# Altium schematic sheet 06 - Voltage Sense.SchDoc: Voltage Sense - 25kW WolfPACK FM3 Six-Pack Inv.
size 431 x 279 mm; Date: 07/2023; DocumentNumber: CRD25DA12N-FMC; Revision: 1.1; SheetNumber: 6; SheetTotal: 8; SheetSize: B
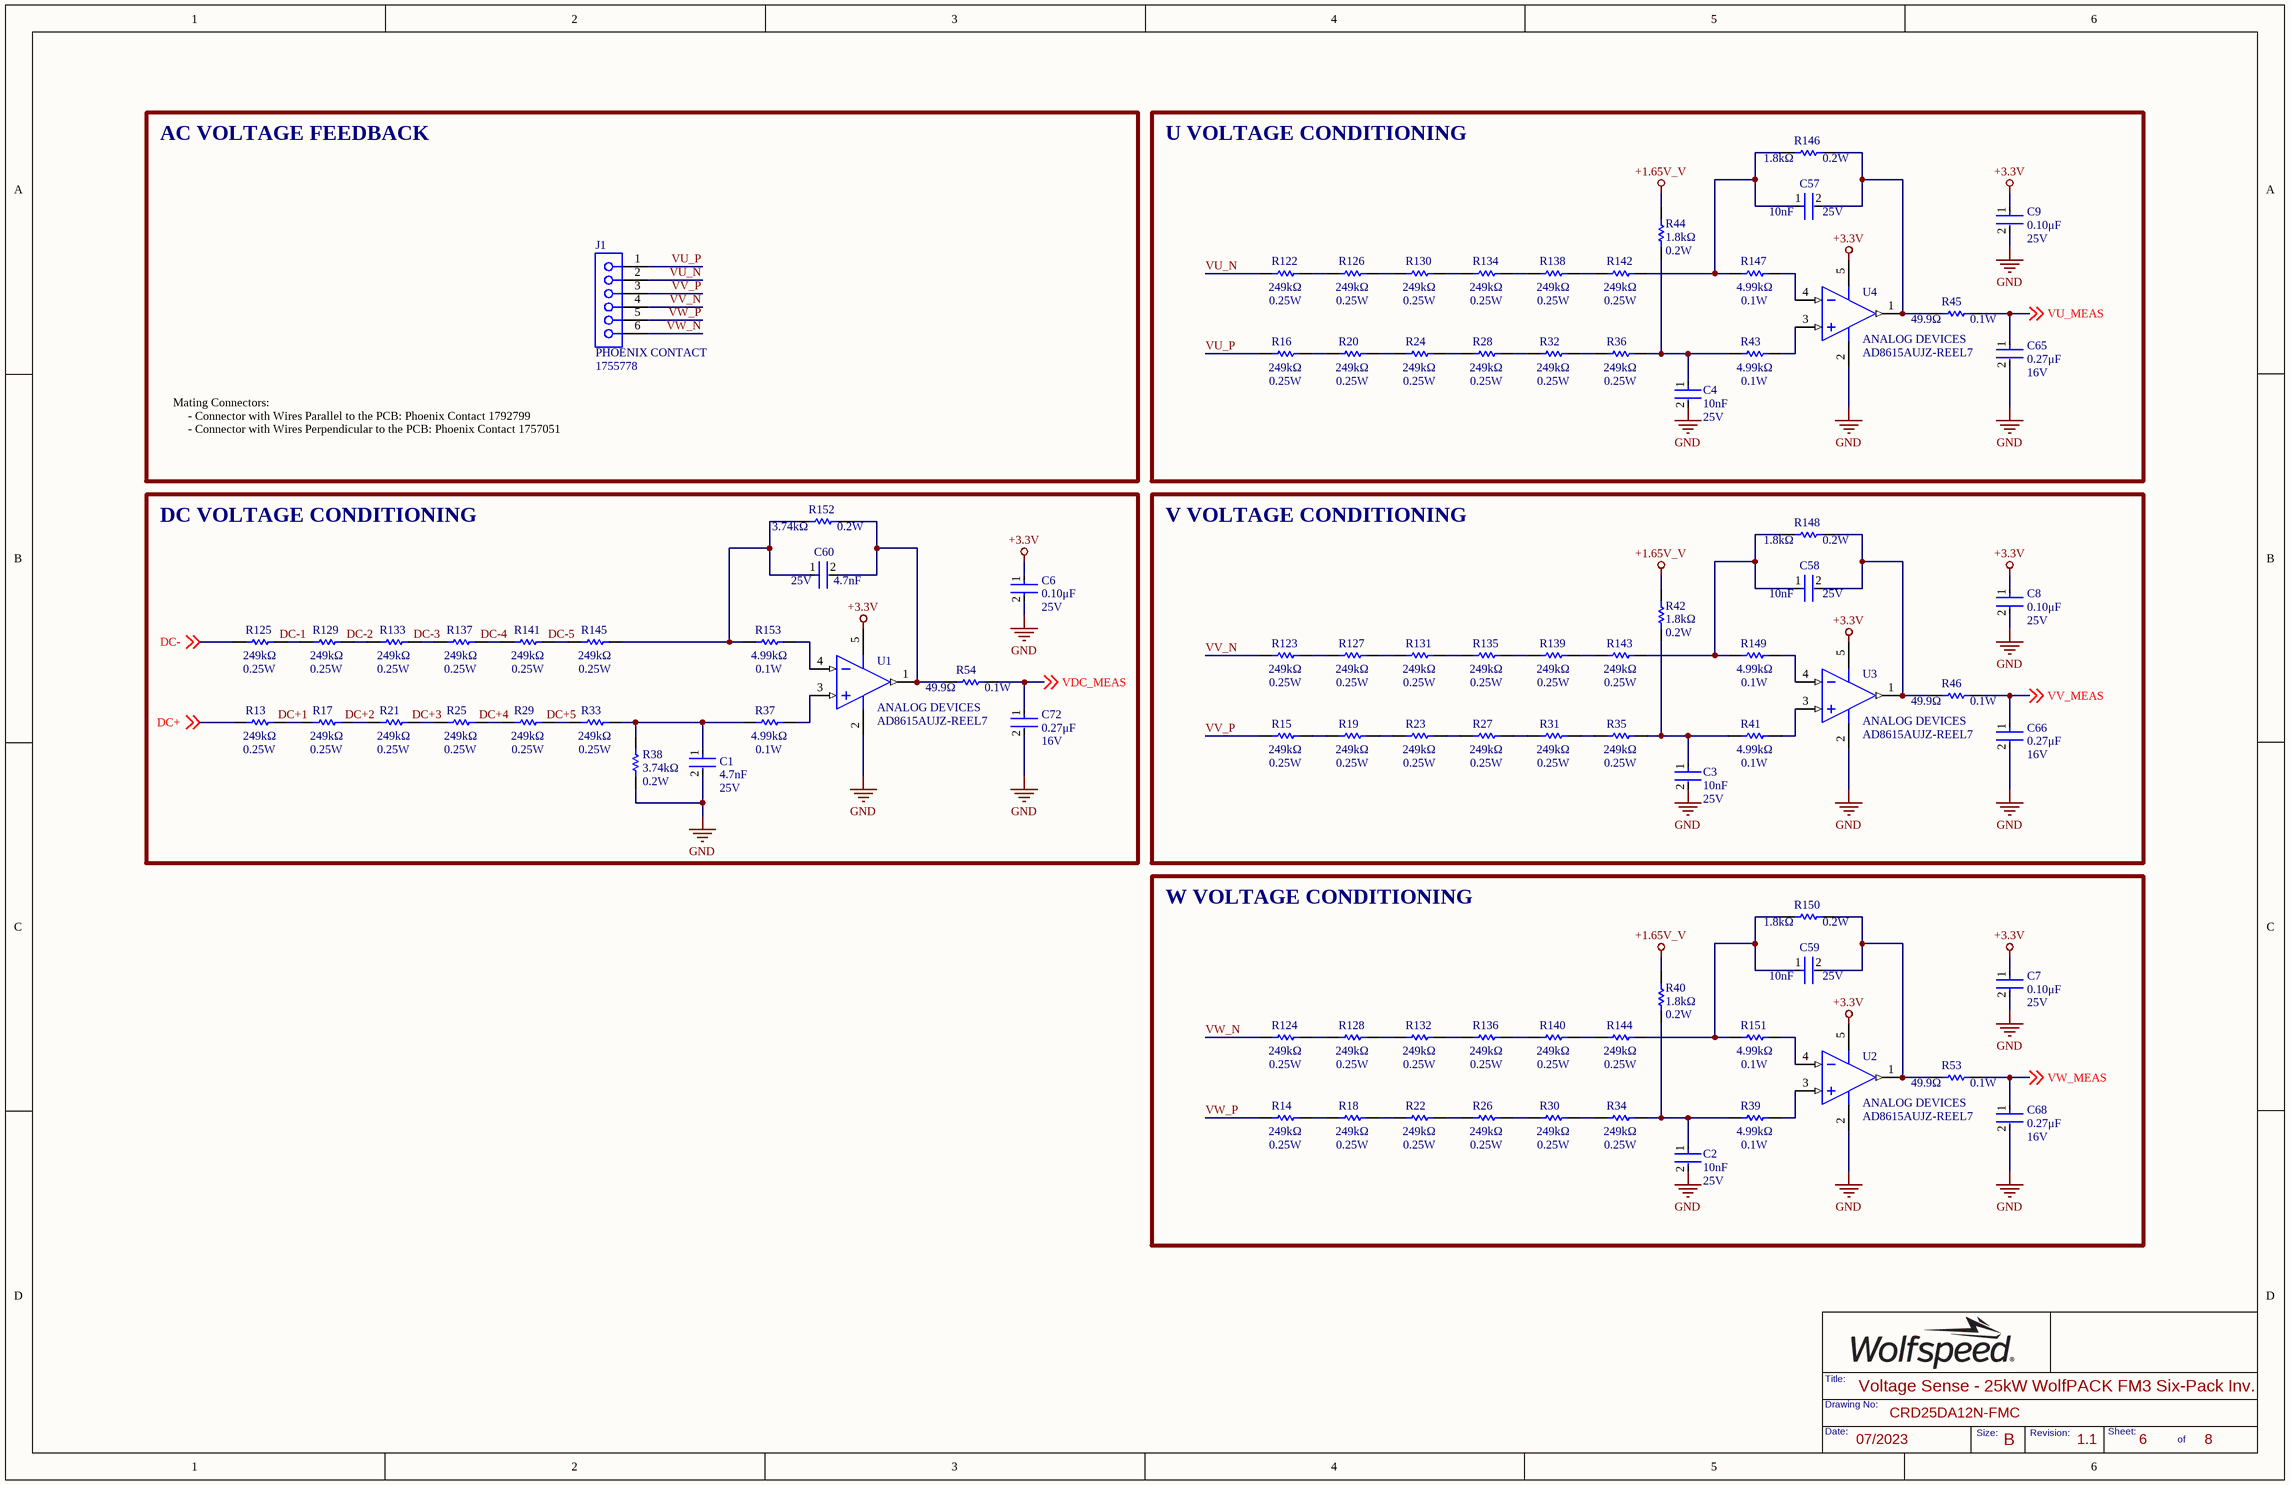
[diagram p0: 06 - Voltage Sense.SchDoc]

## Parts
C1  Voltage Rating: 25V  Capacitance: 4.7nF  [FP-C0603C-CF-IPC_B]  (hidden comment: C0603C472K3RAC7867)
C2  value 10nF  Voltage Rating: 25V  [FP-C0603C-CF-IPC_B]  (hidden comment: CL10B103KA8WPNC)
C3  value 10nF  Voltage Rating: 25V  [FP-C0603C-CF-IPC_B]  (hidden comment: CL10B103KA8WPNC)
C4  value 10nF  Voltage Rating: 25V  [FP-C0603C-CF-IPC_B]  (hidden comment: CL10B103KA8WPNC)
C6  Voltage Rating: 25V  Capacitance: 0.10μF  [FP-C0603C-CF-IPC_B]  (hidden comment: C0603C104K3RACTU)
C7  Voltage Rating: 25V  Capacitance: 0.10μF  [FP-C0603C-CF-IPC_B]  (hidden comment: C0603C104K3RACTU)
C8  Voltage Rating: 25V  Capacitance: 0.10μF  [FP-C0603C-CF-IPC_B]  (hidden comment: C0603C104K3RACTU)
C9  Voltage Rating: 25V  Capacitance: 0.10μF  [FP-C0603C-CF-IPC_B]  (hidden comment: C0603C104K3RACTU)
C57  value 10nF  Voltage Rating: 25V  [FP-C0603C-CF-IPC_B]  (hidden comment: CL10B103KA8WPNC)
C58  value 10nF  Voltage Rating: 25V  [FP-C0603C-CF-IPC_B]  (hidden comment: CL10B103KA8WPNC)
C59  value 10nF  Voltage Rating: 25V  [FP-C0603C-CF-IPC_B]  (hidden comment: CL10B103KA8WPNC)
C60  Voltage Rating: 25V  Capacitance: 4.7nF  [FP-C0603C-CF-IPC_B]  (hidden comment: C0603C472K3RAC7867)
C65  Voltage Rating (DC): 16V  Capacitance: 0.27μF  [FP-GCM188-0_1-IPC_A]  (hidden comment: GCM188R71C274KA37D)
C66  Voltage Rating (DC): 16V  Capacitance: 0.27μF  [FP-GCM188-0_1-IPC_A]  (hidden comment: GCM188R71C274KA37D)
C68  Voltage Rating (DC): 16V  Capacitance: 0.27μF  [FP-GCM188-0_1-IPC_A]  (hidden comment: GCM188R71C274KA37D)
C72  Voltage Rating (DC): 16V  Capacitance: 0.27μF  [FP-GCM188-0_1-IPC_A]  (hidden comment: GCM188R71C274KA37D)
J1  1755778  Manufacturer Print: PHOENIX CONTACT  [1755778]
R13  Resistance: 249kΩ  Power: 0.25W  [RESC3216X65X50NL15T25]  (hidden comment: TNPW1206249KBEEA)
R14  Resistance: 249kΩ  Power: 0.25W  [RESC3216X65X50NL15T25]  (hidden comment: TNPW1206249KBEEA)
R15  Resistance: 249kΩ  Power: 0.25W  [RESC3216X65X50NL15T25]  (hidden comment: TNPW1206249KBEEA)
R16  Resistance: 249kΩ  Power: 0.25W  [RESC3216X65X50NL15T25]  (hidden comment: TNPW1206249KBEEA)
R17  Resistance: 249kΩ  Power: 0.25W  [RESC3216X65X50NL15T25]  (hidden comment: TNPW1206249KBEEA)
R18  Resistance: 249kΩ  Power: 0.25W  [RESC3216X65X50NL15T25]  (hidden comment: TNPW1206249KBEEA)
R19  Resistance: 249kΩ  Power: 0.25W  [RESC3216X65X50NL15T25]  (hidden comment: TNPW1206249KBEEA)
R20  Resistance: 249kΩ  Power: 0.25W  [RESC3216X65X50NL15T25]  (hidden comment: TNPW1206249KBEEA)
R21  Resistance: 249kΩ  Power: 0.25W  [RESC3216X65X50NL15T25]  (hidden comment: TNPW1206249KBEEA)
R22  Resistance: 249kΩ  Power: 0.25W  [RESC3216X65X50NL15T25]  (hidden comment: TNPW1206249KBEEA)
R23  Resistance: 249kΩ  Power: 0.25W  [RESC3216X65X50NL15T25]  (hidden comment: TNPW1206249KBEEA)
R24  Resistance: 249kΩ  Power: 0.25W  [RESC3216X65X50NL15T25]  (hidden comment: TNPW1206249KBEEA)
R25  Resistance: 249kΩ  Power: 0.25W  [RESC3216X65X50NL15T25]  (hidden comment: TNPW1206249KBEEA)
R26  Resistance: 249kΩ  Power: 0.25W  [RESC3216X65X50NL15T25]  (hidden comment: TNPW1206249KBEEA)
R27  Resistance: 249kΩ  Power: 0.25W  [RESC3216X65X50NL15T25]  (hidden comment: TNPW1206249KBEEA)
R28  Resistance: 249kΩ  Power: 0.25W  [RESC3216X65X50NL15T25]  (hidden comment: TNPW1206249KBEEA)
R29  Resistance: 249kΩ  Power: 0.25W  [RESC3216X65X50NL15T25]  (hidden comment: TNPW1206249KBEEA)
R30  Resistance: 249kΩ  Power: 0.25W  [RESC3216X65X50NL15T25]  (hidden comment: TNPW1206249KBEEA)
R31  Resistance: 249kΩ  Power: 0.25W  [RESC3216X65X50NL15T25]  (hidden comment: TNPW1206249KBEEA)
R32  Resistance: 249kΩ  Power: 0.25W  [RESC3216X65X50NL15T25]  (hidden comment: TNPW1206249KBEEA)
R33  Resistance: 249kΩ  Power: 0.25W  [RESC3216X65X50NL15T25]  (hidden comment: TNPW1206249KBEEA)
R34  Resistance: 249kΩ  Power: 0.25W  [RESC3216X65X50NL15T25]  (hidden comment: TNPW1206249KBEEA)
R35  Resistance: 249kΩ  Power: 0.25W  [RESC3216X65X50NL15T25]  (hidden comment: TNPW1206249KBEEA)
R36  Resistance: 249kΩ  Power: 0.25W  [RESC3216X65X50NL15T25]  (hidden comment: TNPW1206249KBEEA)
R37  Power Rating: 0.1W  Resistance: 4.99kΩ  [FP-MCR03-IPC_B]  (hidden comment: RC0603FR-074K99L)
R38  Max Power Dissipation: 0.2W  Resistance: 3.74kΩ  [FP-MCR03-IPC_B]  (hidden comment: ERJ-PB3B3741V)
R39  Power Rating: 0.1W  Resistance: 4.99kΩ  [FP-MCR03-IPC_B]  (hidden comment: RC0603FR-074K99L)
R40  Resistance: 1.8kΩ  Max Power Dissipation: 0.2W  [FP-MCR03-IPC_B]  (hidden comment: ERJ-PB3B1801V)
R41  Power Rating: 0.1W  Resistance: 4.99kΩ  [FP-MCR03-IPC_B]  (hidden comment: RC0603FR-074K99L)
R42  Resistance: 1.8kΩ  Max Power Dissipation: 0.2W  [FP-MCR03-IPC_B]  (hidden comment: ERJ-PB3B1801V)
R43  Power Rating: 0.1W  Resistance: 4.99kΩ  [FP-MCR03-IPC_B]  (hidden comment: RC0603FR-074K99L)
R44  Resistance: 1.8kΩ  Max Power Dissipation: 0.2W  [FP-MCR03-IPC_B]  (hidden comment: ERJ-PB3B1801V)
R45  Resistance: 49.9Ω  Power Rating: 0.1W  [FP-MCR03-IPC_B]  (hidden comment: ERJ-3EKF49R9V)
R46  Resistance: 49.9Ω  Power Rating: 0.1W  [FP-MCR03-IPC_B]  (hidden comment: ERJ-3EKF49R9V)
R53  Resistance: 49.9Ω  Power Rating: 0.1W  [FP-MCR03-IPC_B]  (hidden comment: ERJ-3EKF49R9V)
R54  Resistance: 49.9Ω  Power Rating: 0.1W  [FP-MCR03-IPC_B]  (hidden comment: ERJ-3EKF49R9V)
R122  Resistance: 249kΩ  Power: 0.25W  [RESC3216X65X50NL15T25]  (hidden comment: TNPW1206249KBEEA)
R123  Resistance: 249kΩ  Power: 0.25W  [RESC3216X65X50NL15T25]  (hidden comment: TNPW1206249KBEEA)
R124  Resistance: 249kΩ  Power: 0.25W  [RESC3216X65X50NL15T25]  (hidden comment: TNPW1206249KBEEA)
R125  Resistance: 249kΩ  Power: 0.25W  [RESC3216X65X50NL15T25]  (hidden comment: TNPW1206249KBEEA)
R126  Resistance: 249kΩ  Power: 0.25W  [RESC3216X65X50NL15T25]  (hidden comment: TNPW1206249KBEEA)
R127  Resistance: 249kΩ  Power: 0.25W  [RESC3216X65X50NL15T25]  (hidden comment: TNPW1206249KBEEA)
R128  Resistance: 249kΩ  Power: 0.25W  [RESC3216X65X50NL15T25]  (hidden comment: TNPW1206249KBEEA)
R129  Resistance: 249kΩ  Power: 0.25W  [RESC3216X65X50NL15T25]  (hidden comment: TNPW1206249KBEEA)
R130  Resistance: 249kΩ  Power: 0.25W  [RESC3216X65X50NL15T25]  (hidden comment: TNPW1206249KBEEA)
R131  Resistance: 249kΩ  Power: 0.25W  [RESC3216X65X50NL15T25]  (hidden comment: TNPW1206249KBEEA)
R132  Resistance: 249kΩ  Power: 0.25W  [RESC3216X65X50NL15T25]  (hidden comment: TNPW1206249KBEEA)
R133  Resistance: 249kΩ  Power: 0.25W  [RESC3216X65X50NL15T25]  (hidden comment: TNPW1206249KBEEA)
R134  Resistance: 249kΩ  Power: 0.25W  [RESC3216X65X50NL15T25]  (hidden comment: TNPW1206249KBEEA)
R135  Resistance: 249kΩ  Power: 0.25W  [RESC3216X65X50NL15T25]  (hidden comment: TNPW1206249KBEEA)
R136  Resistance: 249kΩ  Power: 0.25W  [RESC3216X65X50NL15T25]  (hidden comment: TNPW1206249KBEEA)
R137  Resistance: 249kΩ  Power: 0.25W  [RESC3216X65X50NL15T25]  (hidden comment: TNPW1206249KBEEA)
R138  Resistance: 249kΩ  Power: 0.25W  [RESC3216X65X50NL15T25]  (hidden comment: TNPW1206249KBEEA)
R139  Resistance: 249kΩ  Power: 0.25W  [RESC3216X65X50NL15T25]  (hidden comment: TNPW1206249KBEEA)
R140  Resistance: 249kΩ  Power: 0.25W  [RESC3216X65X50NL15T25]  (hidden comment: TNPW1206249KBEEA)
R141  Resistance: 249kΩ  Power: 0.25W  [RESC3216X65X50NL15T25]  (hidden comment: TNPW1206249KBEEA)
R142  Resistance: 249kΩ  Power: 0.25W  [RESC3216X65X50NL15T25]  (hidden comment: TNPW1206249KBEEA)
R143  Resistance: 249kΩ  Power: 0.25W  [RESC3216X65X50NL15T25]  (hidden comment: TNPW1206249KBEEA)
R144  Resistance: 249kΩ  Power: 0.25W  [RESC3216X65X50NL15T25]  (hidden comment: TNPW1206249KBEEA)
R145  Resistance: 249kΩ  Power: 0.25W  [RESC3216X65X50NL15T25]  (hidden comment: TNPW1206249KBEEA)
R146  Resistance: 1.8kΩ  Max Power Dissipation: 0.2W  [FP-MCR03-IPC_B]  (hidden comment: ERJ-PB3B1801V)
R147  Power Rating: 0.1W  Resistance: 4.99kΩ  [FP-MCR03-IPC_B]  (hidden comment: RC0603FR-074K99L)
R148  Resistance: 1.8kΩ  Max Power Dissipation: 0.2W  [FP-MCR03-IPC_B]  (hidden comment: ERJ-PB3B1801V)
R149  Power Rating: 0.1W  Resistance: 4.99kΩ  [FP-MCR03-IPC_B]  (hidden comment: RC0603FR-074K99L)
R150  Resistance: 1.8kΩ  Max Power Dissipation: 0.2W  [FP-MCR03-IPC_B]  (hidden comment: ERJ-PB3B1801V)
R151  Power Rating: 0.1W  Resistance: 4.99kΩ  [FP-MCR03-IPC_B]  (hidden comment: RC0603FR-074K99L)
R152  Max Power Dissipation: 0.2W  Resistance: 3.74kΩ  [FP-MCR03-IPC_B]  (hidden comment: ERJ-PB3B3741V)
R153  Power Rating: 0.1W  Resistance: 4.99kΩ  [FP-MCR03-IPC_B]  (hidden comment: RC0603FR-074K99L)
U1  Manufacturer: ANALOG DEVICES  [ADI-UJ-5_M]  (hidden comment: AD8615AUJZ-REEL7)
U2  Manufacturer: ANALOG DEVICES  [ADI-UJ-5_M]  (hidden comment: AD8615AUJZ-REEL7)
U3  Manufacturer: ANALOG DEVICES  [ADI-UJ-5_M]  (hidden comment: AD8615AUJZ-REEL7)
U4  Manufacturer: ANALOG DEVICES  [ADI-UJ-5_M]  (hidden comment: AD8615AUJZ-REEL7)

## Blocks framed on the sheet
AC VOLTAGE FEEDBACK: J1
U VOLTAGE CONDITIONING: C4 C9 C57 C65 R16 R20 R24 R28 R32 R36 R43-R45 R122 R126 R130 R134 R138 R142 R146 R147 U4
DC VOLTAGE CONDITIONING: C1 C6 C60 C72 R13 R17 R21 R25 R29 R33 R37 R38 R54 R125 R129 R133 R137 R141 R145 R152 R153 U1
V VOLTAGE CONDITIONING: C3 C8 C58 C66 R15 R19 R23 R27 R31 R35 R41 R42 R46 R123 R127 R131 R135 R139 R143 R148 R149 U3
W VOLTAGE CONDITIONING: C2 C7 C59 C68 R14 R18 R22 R26 R30 R34 R39 R40 R53 R124 R128 R132 R136 R140 R144 R150 R151 U2

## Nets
+1.65V_V: R40.2 R42.2 R44.2
+3.3V: C6.1 C7.1 C8.1 C9.1 U1.5(+V) U2.5(+V) U3.5(+V) U4.5(+V)
GND: C1.2 C2.2 C3.2 C4.2 C6.2 C7.2 C8.2 C9.2 C65.2 C66.2 C68.2 C72.2 R38.1 U1.2(-V) U2.2(-V) U3.2(-V) U4.2(-V)
DC+: R13.1 ; off-sheet DC+
DC+1: R13.2 R17.1
DC+2: R17.2 R21.1
DC+3: R21.2 R25.1
DC+4: R25.2 R29.1
DC+5: R29.2 R33.1
DC-: R125.1 ; off-sheet DC-
DC-1: R125.2 R129.1
DC-2: R129.2 R133.1
DC-3: R133.2 R137.1
DC-4: R137.2 R141.1
DC-5: R141.2 R145.1
VDC_MEAS: C72.1 R54.2 ; off-sheet VDC_MEAS
VU_MEAS: C65.1 R45.2 ; off-sheet VU_MEAS
VU_N: J1.2 R122.1
VU_P: J1.1 R16.1
VV_MEAS: C66.1 R46.2 ; off-sheet VV_MEAS
VV_N: J1.4 R123.1
VV_P: J1.3 R15.1
VW_MEAS: C68.1 R53.2 ; off-sheet VW_MEAS
VW_N: J1.6 R124.1
VW_P: J1.5 R14.1
NetC1_1: C1.1 R33.2 R37.1 R38.2
NetC2_1: C2.1 R34.2 R39.1 R40.1
NetC3_1: C3.1 R35.2 R41.1 R42.1
NetC4_1: C4.1 R36.2 R43.1 R44.1
NetC57_1: C57.1 R142.2 R146.2 R147.1
NetC57_2: C57.2 R45.1 R146.1 U4.1(OUT)
NetC58_1: C58.1 R143.2 R148.2 R149.1
NetC58_2: C58.2 R46.1 R148.1 U3.1(OUT)
NetC59_1: C59.1 R144.2 R150.2 R151.1
NetC59_2: C59.2 R53.1 R150.1 U2.1(OUT)
NetC60_1: C60.1 R145.2 R152.1 R153.1
NetC60_2: C60.2 R54.1 R152.2 U1.1(OUT)
NetR14_2: R14.2 R18.1
NetR15_2: R15.2 R19.1
NetR16_2: R16.2 R20.1
NetR18_2: R18.2 R22.1
NetR19_2: R19.2 R23.1
NetR20_2: R20.2 R24.1
NetR22_2: R22.2 R26.1
NetR23_2: R23.2 R27.1
NetR24_2: R24.2 R28.1
NetR26_2: R26.2 R30.1
NetR27_2: R27.2 R31.1
NetR28_2: R28.2 R32.1
NetR30_2: R30.2 R34.1
NetR31_2: R31.2 R35.1
NetR32_2: R32.2 R36.1
NetR37_2: R37.2 U1.3(+IN)
NetR39_2: R39.2 U2.3(+IN)
NetR41_2: R41.2 U3.3(+IN)
NetR43_2: R43.2 U4.3(+IN)
NetR122_2: R122.2 R126.1
NetR123_2: R123.2 R127.1
NetR124_2: R124.2 R128.1
NetR126_2: R126.2 R130.1
NetR127_2: R127.2 R131.1
NetR128_2: R128.2 R132.1
NetR130_2: R130.2 R134.1
NetR131_2: R131.2 R135.1
NetR132_2: R132.2 R136.1
NetR134_2: R134.2 R138.1
NetR135_2: R135.2 R139.1
NetR136_2: R136.2 R140.1
NetR138_2: R138.2 R142.1
NetR139_2: R139.2 R143.1
NetR140_2: R140.2 R144.1
NetR147_2: R147.2 U4.4(-IN)
NetR149_2: R149.2 U3.4(-IN)
NetR151_2: R151.2 U2.4(-IN)
NetR153_2: R153.2 U1.4(-IN)

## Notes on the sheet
- Mating Connectors:
  - Connector with Wires Parallel to the PCB: Phoenix Contact 1792799
  - Connector with Wires Perpendicular to the PCB: Phoenix Contact 1757051

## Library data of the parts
C1 C60 = C0603C472K3RAC7867: CAP CER 4700PF 25V 10% X7R 0603; Manufacturer: KEMET; Manufacturer Part Number: C0603C472K3RACTU; Dielectric Material: Ceramic; Value: 4.7nF
C2-C4 C57-C59 = CL10B103KA8WPNC: CAP CER 10000PF 25V X7R 0603; Manufacturer: SAMSUNG; Tolerance: 10%
C6-C9 = CMP-2006-03057-2: CAP CER 0.1UF 25V X7R 0603; Manufacturer: KEMET; Value: 0.10μF; Material: Ceramic; Tolerance: 0.1; Temperature Coefficient: 30ppm/°C; Automotive Grade: Grade 1
C65 C66 C68 C72 = CMP-06035-043171-1: CAP CER 0.27UF 16V X7R 0603; Manufacturer: MURATA; Tolerance: 10%; Value: 0.27μF
J1 = 1755778: TERM BLOCK HDR 6POS VERT 5.08MM; Voltage Rating: 250V; Current Rating: 12A; Number of Positions: 6; Number of Levels: 1; Voltage: 300V; Gender: Male; Connector Type: Plug; Approvals: UL,CSA,VDE,cULus,CB,EAC
R13-R36 R122-R145 = CMP-2003-04604-1: RES 249K OHM 0.1% 1/4W 1206; Manufacturer: VISHAY DALE; Value: 249kΩ
R37 R39 R41 R43 R147 R149 R151 R153 = RC0603FR-074K99L: RES 4.99K OHM 1% 1/10W 0603; Manufacturer: YAGEO; Voltage Rating: 75V; Temperature Coefficient: 100ppm/°C; Voltage Rating (DC): 50V; Value: 4.99kΩ
R38 R152 = ERJ-PB3B3741V: RES SMD 3.74K OHM 0.1% 1/5W 0603; Manufacturer: PANASONIC; Temperature Coefficient: 50ppm/°C; Value: 3.74kΩ
R40 R42 R44 R146 R148 R150 = ERJ-PB3B1801V: RES SMD 1.8K OHM 0.1% 1/5W 0603; Manufacturer: PANASONIC; Temperature Coefficient: 50ppm/°C; Value: 1.8kΩ
R45 R46 R53 R54 = ERJ-3EKF49R9V: RES SMD 49.9 OHM 1% 1/10W 0603; Manufacturer: PANASONIC; Temperature Coefficient: 100ppm/°C; Voltage Rating: 75V; Max Power Dissipation: 100mW; Voltage Rating (DC): 50V; Working Voltage: 6V; Value: 49.9Ω
U1-U4 = CMP-0384-02059-2: IC OPAMP GP 1 CIRCUIT TSOT23-5; Generic Part Number: AD8615; Iq/Amp: 1.7mA; V Span Max: 6V; Amplifiers Per Package: 1; Small Signal Bandwidth: 23MHz; Input Offset Voltage: 80uV; V Span Min: 2.7V; Slew Rate: 12V/us; Input Bias Current: 200fA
